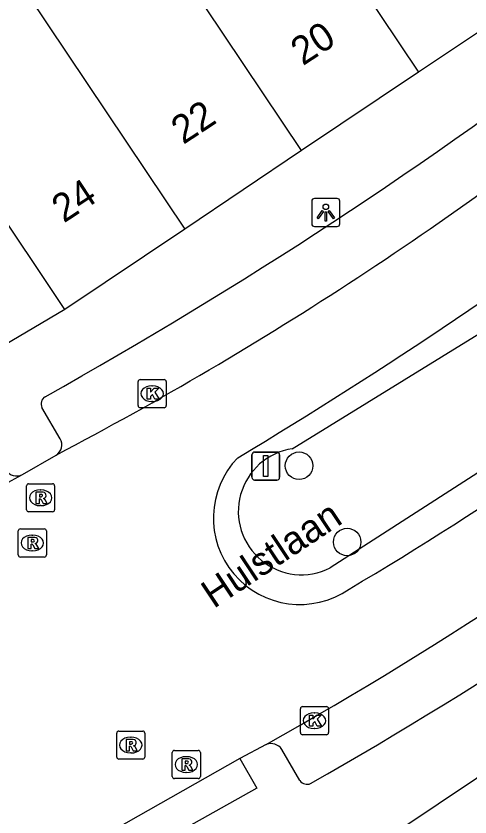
# Model space of a CAD drawing. Extents: x 159718 to 160783, y 383290 to 384030.
# Drawn here: x 160388.58 to 160404.74, y 383529.73 to 383558.24 of the extents above; entities that cross this region are included whole.
import ezdxf

# ---------------------------------------------------------------- set-up
doc = ezdxf.new("R2010")
doc.units = 0
for name, color, linetype in [('IMGEO_Boom', 7, 'Continuous'), ('IMGEO_Groenvoorziening', 7, 'Continuous'), ('IMGEO_Kolk', 7, 'Continuous'), ('IMGEO_Lichtpunt', 7, 'Continuous'), ('IMGEO_Openbare_ruimte_label', 7, 'Continuous'), ('IMGEO_Pand', 7, 'Continuous'), ('IMGEO_Pand_nummerreeks', 7, 'Continuous'), ('IMGEO_Rijbaan_lokaal_open', 7, 'Continuous'), ('IMGEO_Rioolput', 7, 'Continuous'), ('IMGEO_Verkeersbordpaal', 7, 'Continuous'), ('IMGEO_Voetpad_open', 7, 'Continuous')]:
    doc.layers.add(name, color=color, linetype=linetype)

msp = doc.modelspace()

# ---------------------------------------------------------------- linework, layer by layer
at = {"layer": 'IMGEO_Boom'}
for centre in [(160398.654, 383542.237), (160400.367, 383539.522)]:
    msp.add_circle(centre, 0.489, dxfattribs=at)
at = {"layer": 'IMGEO_Groenvoorziening'}
for points in [[(160419.524, 383558.843), (160420.216, 383557.971), (160438.33, 383572.13), (160446.182, 383578.368), (160461.987, 383591.376), (160464.497, 383588.63), (160449.031, 383575.404), (160429.985, 383560.714), (160408.787, 383544.408), (160399.76, 383538.598)], [(160398.414, 383542.841), (160406.387, 383547.75), (160417.838, 383556.217), (160417.152, 383557.006)]]:
    msp.add_lwpolyline(points, dxfattribs=at)
msp.add_arc((160398.746, 383540.611), 2.254, 98.4652, 296.7358, dxfattribs=at)
at = {"layer": 'IMGEO_Kolk'}
for p, q in [((160392.924, 383544.377), (160392.924, 383545.229)), ((160392.999, 383545.303), (160393.851, 383545.303)), ((160393.412, 383545.083), (160393.437, 383545.083)), ((160393.925, 383545.229), (160393.925, 383544.377)), ((160393.435, 383544.523), (160393.41, 383544.523)), ((160393.851, 383544.303), (160392.999, 383544.303)), ((160398.779, 383533.664), (160399.631, 383533.664)), ((160398.704, 383532.738), (160398.704, 383533.59)), ((160399.192, 383533.444), (160399.217, 383533.444)), ((160399.705, 383533.59), (160399.705, 383532.738)), ((160399.215, 383532.884), (160399.19, 383532.884)), ((160399.631, 383532.664), (160398.779, 383532.664))]:
    msp.add_line(p, q, dxfattribs=at)
for points in [[(160392.924, 383544.377), (160392.924, 383545.229)], [(160392.999, 383545.303), (160393.851, 383545.303)], [(160393.925, 383545.229), (160393.925, 383544.377)], [(160393.245, 383545.003), (160393.368, 383545.003), (160393.368, 383544.852), (160393.498, 383545.003), (160393.662, 383545.003), (160393.516, 383544.852), (160393.669, 383544.603), (160393.517, 383544.603), (160393.432, 383544.767), (160393.368, 383544.7), (160393.368, 383544.603), (160393.245, 383544.603), (160393.245, 383545.003)], [(160393.851, 383544.303), (160392.999, 383544.303)], [(160398.779, 383533.664), (160399.631, 383533.664)], [(160398.704, 383532.738), (160398.704, 383533.59)], [(160399.025, 383533.364), (160399.148, 383533.364), (160399.148, 383533.213), (160399.278, 383533.364), (160399.442, 383533.364), (160399.296, 383533.213), (160399.449, 383532.964), (160399.297, 383532.964), (160399.212, 383533.128), (160399.148, 383533.061), (160399.148, 383532.964), (160399.025, 383532.964), (160399.025, 383533.364)], [(160399.705, 383533.59), (160399.705, 383532.738)], [(160399.631, 383532.664), (160398.779, 383532.664)]]:
    msp.add_lwpolyline(points, dxfattribs=at)
for centre, start, end in [((160393.001, 383545.227), 91.552, 178.448), ((160393.001, 383545.227), 91.552, 178.448), ((160393.849, 383545.227), 1.552, 88.448), ((160393.849, 383545.227), 1.552, 88.448), ((160393.001, 383544.379), 181.552, 268.448), ((160393.001, 383544.379), 181.552, 268.448), ((160393.849, 383544.379), 271.552, 358.448), ((160393.849, 383544.379), 271.552, 358.448), ((160398.781, 383533.588), 91.552, 178.448), ((160398.781, 383533.588), 91.552, 178.448), ((160399.629, 383533.588), 1.552, 88.448), ((160399.629, 383533.588), 1.552, 88.448), ((160398.781, 383532.74), 181.552, 268.448), ((160398.781, 383532.74), 181.552, 268.448), ((160399.629, 383532.74), 271.552, 358.448), ((160399.629, 383532.74), 271.552, 358.448)]:
    msp.add_arc(centre, 0.0765, start, end, dxfattribs=at)
for centre, major_axis, ratio, start_param, end_param in [((160393.411, 383544.803), (-0.387, 0.002), 0.722429, 4.712389, 7.853982), ((160393.436, 383544.803), (-0.39, 0.002), 0.717154, 1.570796, 4.712389), ((160399.191, 383533.164), (-0.387, 0.002), 0.722429, 4.712389, 7.853982), ((160399.216, 383533.164), (-0.39, 0.002), 0.717154, 1.570796, 4.712389)]:
    msp.add_ellipse(centre, major_axis=major_axis, ratio=ratio, start_param=start_param, end_param=end_param, dxfattribs=at)
at = {"layer": 'IMGEO_Lichtpunt'}
for p, q in [((160399.109, 383551.653), (160399.109, 383550.846)), ((160399.109, 383551.653), (160399.109, 383550.846)), ((160400.011, 383551.748), (160399.203, 383551.748)), ((160400.011, 383551.748), (160399.203, 383551.748)), ((160400.105, 383550.846), (160400.105, 383551.653)), ((160400.105, 383550.846), (160400.105, 383551.653)), ((160399.203, 383550.752), (160400.011, 383550.752)), ((160399.203, 383550.752), (160400.011, 383550.752))]:
    msp.add_line(p, q, dxfattribs=at)
for points in [[(160399.483, 383551.317), (160399.522, 383551.289), (160399.334, 383551.027), (160399.296, 383551.054), (160399.483, 383551.317)], [(160399.585, 383551.269), (160399.632, 383551.269), (160399.632, 383550.947), (160399.585, 383550.947), (160399.585, 383551.269)], [(160399.695, 383551.289), (160399.733, 383551.316), (160399.92, 383551.054), (160399.881, 383551.026), (160399.695, 383551.289)]]:
    msp.add_lwpolyline(points, dxfattribs=at)
msp.add_circle((160399.608, 383551.451), 0.0994, dxfattribs=at)
for centre, start, end in [((160399.203, 383551.653), 90, 180), ((160399.203, 383551.653), 90, 180), ((160400.011, 383551.653), 0, 90), ((160400.011, 383551.653), 0, 90), ((160399.203, 383550.846), 180, 270), ((160399.203, 383550.846), 180, 270), ((160400.011, 383550.846), 270, 0), ((160400.011, 383550.846), 270, 360)]:
    msp.add_arc(centre, 0.0946, start, end, dxfattribs=at)
at = {"layer": 'IMGEO_Pand'}
for points in [[(160395.028, 383568.006), (160395.3, 383567.6), (160402.914, 383556.244)], [(160386.78, 383562.298), (160386.899, 383562.119), (160394.582, 383550.66)], [(160398.747, 383553.452), (160394.611, 383559.622), (160394.296, 383560.092)], [(160407.177, 383559.102), (160402.914, 383556.244)], [(160402.914, 383556.244), (160398.747, 383553.452)], [(160390.317, 383547.801), (160387.542, 383551.941), (160385.977, 383554.277)], [(160398.747, 383553.452), (160394.582, 383550.66)], [(160394.582, 383550.66), (160390.317, 383547.801)], [(160406.369, 383532.036), (160402.202, 383529.253)]]:
    msp.add_lwpolyline(points, dxfattribs=at)
at = {"layer": 'IMGEO_Rijbaan_lokaal_open'}
for points in [[(160388.804, 383541.926), (160390.004, 383542.616)], [(160397.484, 383532.319), (160396.549, 383531.817)], [(160396.549, 383531.817), (160390.458, 383528.368), (160390.396, 383528.326)]]:
    msp.add_lwpolyline(points, dxfattribs=at)
for centre, radius, start, end in [((160329.831, 383657.155), 129.383, 297.71538, 308.75428), ((160307.745, 383690.615), 172.639, 300.92764, 307.02534), ((160337.874, 383643.733), 122.989, 300.57578, 308.72915), ((160329.015, 383654.541), 140.094, 299.25776, 308.36943), ((160398.683, 383540.377), 3.079, 135.8491, 304.6884), ((160216.107, 383851.258), 354.275, 294.61833, 299.17415)]:
    msp.add_arc(centre, radius, start, end, dxfattribs=at)
at = {"layer": 'IMGEO_Rioolput'}
for p, q in [((160388.951, 383540.67), (160388.951, 383541.522)), ((160389.026, 383541.596), (160389.878, 383541.596)), ((160389.439, 383541.376), (160389.464, 383541.376)), ((160389.952, 383541.522), (160389.952, 383540.67)), ((160389.462, 383540.816), (160389.437, 383540.816)), ((160389.878, 383540.596), (160389.026, 383540.596)), ((160388.732, 383539.988), (160389.584, 383539.988)), ((160388.657, 383539.062), (160388.657, 383539.914)), ((160389.145, 383539.768), (160389.17, 383539.768)), ((160389.658, 383539.914), (160389.658, 383539.062)), ((160389.168, 383539.208), (160389.143, 383539.208)), ((160389.584, 383538.988), (160388.732, 383538.988)), ((160392.237, 383532.794), (160393.089, 383532.794)), ((160392.162, 383531.868), (160392.162, 383532.72)), ((160392.65, 383532.574), (160392.675, 383532.574)), ((160393.163, 383532.72), (160393.163, 383531.868)), ((160392.673, 383532.014), (160392.648, 383532.014)), ((160394.14, 383531.176), (160394.14, 383532.028)), ((160394.215, 383532.102), (160395.067, 383532.102)), ((160395.141, 383532.028), (160395.141, 383531.176)), ((160393.089, 383531.794), (160392.237, 383531.794)), ((160394.628, 383531.882), (160394.653, 383531.882)), ((160395.067, 383531.102), (160394.215, 383531.102)), ((160394.651, 383531.322), (160394.626, 383531.322))]:
    msp.add_line(p, q, dxfattribs=at)
for points in [[(160388.951, 383540.67), (160388.951, 383541.522)], [(160389.026, 383541.596), (160389.878, 383541.596)], [(160389.952, 383541.522), (160389.952, 383540.67)], [(160389.54, 383541.294), (160389.288, 383541.296), (160389.288, 383540.896)], [(160389.288, 383540.896), (160389.412, 383540.896), (160389.412, 383541.058), (160389.423, 383541.058)], [(160389.466, 383541.215), (160389.412, 383541.215), (160389.412, 383541.134)], [(160389.412, 383541.134), (160389.464, 383541.134)], [(160389.47, 383541.029), (160389.541, 383540.896), (160389.681, 383540.896), (160389.616, 383541.022)], [(160389.878, 383540.596), (160389.026, 383540.596)], [(160388.732, 383539.988), (160389.584, 383539.988)], [(160388.657, 383539.062), (160388.657, 383539.914)], [(160389.246, 383539.686), (160388.994, 383539.688), (160388.994, 383539.288)], [(160389.658, 383539.914), (160389.658, 383539.062)], [(160388.994, 383539.288), (160389.118, 383539.288), (160389.118, 383539.45), (160389.129, 383539.45)], [(160389.172, 383539.607), (160389.118, 383539.607), (160389.118, 383539.526)], [(160389.118, 383539.526), (160389.17, 383539.526)], [(160389.176, 383539.421), (160389.247, 383539.288), (160389.387, 383539.288), (160389.322, 383539.414)], [(160389.584, 383538.988), (160388.732, 383538.988)], [(160392.237, 383532.794), (160393.089, 383532.794)], [(160392.162, 383531.868), (160392.162, 383532.72)], [(160393.163, 383532.72), (160393.163, 383531.868)], [(160392.751, 383532.492), (160392.499, 383532.494), (160392.499, 383532.094)], [(160392.499, 383532.094), (160392.623, 383532.094), (160392.623, 383532.256), (160392.634, 383532.256)], [(160392.677, 383532.413), (160392.623, 383532.413), (160392.623, 383532.332)], [(160392.623, 383532.332), (160392.675, 383532.332)], [(160392.681, 383532.227), (160392.752, 383532.094), (160392.892, 383532.094), (160392.827, 383532.22)], [(160394.14, 383531.176), (160394.14, 383532.028)], [(160394.215, 383532.102), (160395.067, 383532.102)], [(160395.141, 383532.028), (160395.141, 383531.176)], [(160393.089, 383531.794), (160392.237, 383531.794)], [(160394.729, 383531.8), (160394.477, 383531.802), (160394.477, 383531.402)], [(160394.655, 383531.721), (160394.601, 383531.721), (160394.601, 383531.64)], [(160394.477, 383531.402), (160394.601, 383531.402), (160394.601, 383531.564), (160394.612, 383531.564)], [(160394.601, 383531.64), (160394.653, 383531.64)], [(160394.659, 383531.535), (160394.73, 383531.402), (160394.87, 383531.402), (160394.805, 383531.528)], [(160395.067, 383531.102), (160394.215, 383531.102)]]:
    msp.add_lwpolyline(points, dxfattribs=at)
for centre, radius, start, end in [((160389.028, 383541.52), 0.0765, 91.552, 178.448), ((160389.028, 383541.52), 0.0765, 91.552, 178.448), ((160389.876, 383541.52), 0.0765, 1.552, 88.448), ((160389.876, 383541.52), 0.0765, 1.552, 88.448), ((160389.422, 383541.005), 0.0533, 26.0293, 88.6989), ((160389.448, 383541.323), 0.19, 274.7715, 282.9687), ((160389.472, 383541.119), 0.0964, 77.0061, 93.1865), ((160389.486, 383541.176), 0.0378, 276.6634, 79.6772), ((160389.539, 383541.184), 0.109, 350.3612, 89.416), ((160389.537, 383541.184), 0.112, 277.5842, 350.9817), ((160389.521, 383540.969), 0.108, 29.5134, 73.7905), ((160389.028, 383540.672), 0.0765, 181.552, 268.448), ((160389.028, 383540.672), 0.0765, 181.552, 268.448), ((160389.876, 383540.672), 0.0765, 271.552, 358.448), ((160389.876, 383540.672), 0.0765, 271.552, 358.448), ((160388.734, 383539.912), 0.0765, 91.552, 178.448), ((160388.734, 383539.912), 0.0765, 91.552, 178.448), ((160389.582, 383539.912), 0.0765, 1.552, 88.448), ((160389.582, 383539.912), 0.0765, 1.552, 88.448), ((160389.245, 383539.576), 0.109, 350.3612, 89.416), ((160389.128, 383539.397), 0.0533, 26.0293, 88.6989), ((160389.154, 383539.715), 0.19, 274.7715, 282.9687), ((160389.178, 383539.511), 0.0964, 77.0061, 93.1865), ((160389.192, 383539.568), 0.0378, 276.6634, 79.6772), ((160389.243, 383539.576), 0.112, 277.5842, 350.9817), ((160389.227, 383539.361), 0.108, 29.5134, 73.7905), ((160388.734, 383539.064), 0.0765, 181.552, 268.448), ((160388.734, 383539.064), 0.0765, 181.552, 268.448), ((160389.582, 383539.064), 0.0765, 271.552, 358.448), ((160389.582, 383539.064), 0.0765, 271.552, 358.448), ((160392.239, 383532.718), 0.0765, 91.552, 178.448), ((160392.239, 383532.718), 0.0765, 91.552, 178.448), ((160393.087, 383532.718), 0.0765, 1.552, 88.448), ((160393.087, 383532.718), 0.0765, 1.552, 88.448), ((160392.633, 383532.203), 0.0533, 26.0293, 88.6989), ((160392.659, 383532.521), 0.19, 274.7715, 282.9687), ((160392.683, 383532.317), 0.0964, 77.0061, 93.1865), ((160392.697, 383532.374), 0.0378, 276.6634, 79.6772), ((160392.75, 383532.382), 0.109, 350.3612, 89.416), ((160392.748, 383532.382), 0.112, 277.5842, 350.9817), ((160392.732, 383532.167), 0.108, 29.5134, 73.7905), ((160394.217, 383532.026), 0.0765, 91.552, 178.448), ((160394.217, 383532.026), 0.0765, 91.552, 178.448), ((160395.065, 383532.026), 0.0765, 1.552, 88.448), ((160395.065, 383532.026), 0.0765, 1.552, 88.448), ((160392.239, 383531.87), 0.0765, 181.552, 268.448), ((160392.239, 383531.87), 0.0765, 181.552, 268.448), ((160393.087, 383531.87), 0.0765, 271.552, 358.448), ((160393.087, 383531.87), 0.0765, 271.552, 358.448), ((160394.661, 383531.625), 0.0964, 77.0061, 93.1865), ((160394.675, 383531.682), 0.0378, 276.6634, 79.6772), ((160394.728, 383531.69), 0.109, 350.3612, 89.416), ((160394.726, 383531.69), 0.112, 277.5842, 350.9817), ((160394.611, 383531.511), 0.0533, 26.0293, 88.6989), ((160394.637, 383531.829), 0.19, 274.7715, 282.9687), ((160394.71, 383531.475), 0.108, 29.5134, 73.7905), ((160394.217, 383531.178), 0.0765, 181.552, 268.448), ((160394.217, 383531.178), 0.0765, 181.552, 268.448), ((160395.065, 383531.178), 0.0765, 271.552, 358.448), ((160395.065, 383531.178), 0.0765, 271.552, 358.448)]:
    msp.add_arc(centre, radius, start, end, dxfattribs=at)
for centre, major_axis, ratio, start_param, end_param in [((160389.438, 383541.096), (-0.387, 0.002), 0.722429, 4.712389, 7.853982), ((160389.463, 383541.096), (-0.39, 0.002), 0.717154, 1.570796, 4.712389), ((160389.144, 383539.488), (-0.387, 0.002), 0.722429, 4.712389, 7.853982), ((160389.169, 383539.488), (-0.39, 0.002), 0.717154, 1.570796, 4.712389), ((160392.649, 383532.294), (-0.387, 0.002), 0.722429, 4.712389, 7.853982), ((160392.674, 383532.294), (-0.39, 0.002), 0.717154, 1.570796, 4.712389), ((160394.627, 383531.602), (-0.387, 0.002), 0.722429, 4.712389, 7.853982), ((160394.652, 383531.602), (-0.39, 0.002), 0.717154, 1.570796, 4.712389)]:
    msp.add_ellipse(centre, major_axis=major_axis, ratio=ratio, start_param=start_param, end_param=end_param, dxfattribs=at)
at = {"layer": 'IMGEO_Verkeersbordpaal'}
for p, q in [((160396.974, 383541.825), (160396.974, 383542.625)), ((160396.974, 383542.625), (160396.974, 383541.825)), ((160397.074, 383542.725), (160397.864, 383542.725)), ((160397.864, 383542.725), (160397.074, 383542.725)), ((160397.964, 383542.625), (160397.964, 383541.825)), ((160397.964, 383541.825), (160397.964, 383542.625)), ((160397.864, 383541.725), (160397.074, 383541.725)), ((160397.074, 383541.725), (160397.864, 383541.725))]:
    msp.add_line(p, q, dxfattribs=at)
msp.add_lwpolyline([(160397.394, 383542.6), (160397.544, 383542.6), (160397.544, 383541.85), (160397.394, 383541.85), (160397.394, 383542.6)], dxfattribs=at)
for centre, start, end in [((160397.074, 383542.625), 90, 180), ((160397.074, 383542.625), 90, 180), ((160397.864, 383542.625), 0, 90), ((160397.864, 383542.625), 360, 90), ((160397.074, 383541.825), 180, 270), ((160397.074, 383541.825), 180, 270), ((160397.864, 383541.825), 270, 0), ((160397.864, 383541.825), 270, 0)]:
    msp.add_arc(centre, 0.1, start, end, dxfattribs=at)
at = {"layer": 'IMGEO_Voetpad_open'}
for points in [[(160390.317, 383547.801), (160384.265, 383544.222)], [(160390.143, 383543.198), (160389.5, 383544.305)], [(160398.688, 383531.031), (160398.047, 383532.141)], [(160396.549, 383531.817), (160397.15, 383530.763), (160390.613, 383527.099)]]:
    msp.add_lwpolyline(points, dxfattribs=at)
for centre, radius, start, end in [((160307.998, 383690.896), 167.438, 299.17088, 307.37765), ((160389.769, 383544.439), 0.301, 121.9603, 206.4604), ((160389.79, 383542.975), 0.418, 300.8241, 32.3111), ((160319.736, 383670.252), 160.33, 299.65688, 307.5105), ((160388.593, 383542.322), 0.449, 212.9484, 298.0639), ((160397.647, 383531.856), 0.491, 35.4536, 109.4563), ((160398.943, 383531.209), 0.311, 214.9397, 293.6081)]:
    msp.add_arc(centre, radius, start, end, dxfattribs=at)

# ---------------------------------------------------------------- texts
at = {"layer": 'IMGEO_Openbare_ruimte_label'}
msp.add_text('Hulstlaan', height=1, rotation=33.5788, dxfattribs=at).set_placement((160395.615, 383537.134))
at = {"layer": 'IMGEO_Pand_nummerreeks'}
for s, p in [('20', (160398.791, 383556.454)), ('22', (160394.533, 383553.652)), ('24', (160390.281, 383550.857))]:
    msp.add_text(s, height=1, rotation=33.3347, dxfattribs=at).set_placement(p)

doc.saveas('drawing.dxf')
